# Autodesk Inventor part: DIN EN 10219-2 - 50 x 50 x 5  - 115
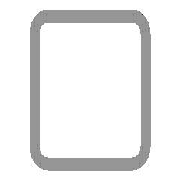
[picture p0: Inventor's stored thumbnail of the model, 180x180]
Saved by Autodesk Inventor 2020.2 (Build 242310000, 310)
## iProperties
IsCustomPart: 1
_CCFamilyMember: 16
_CCFamilyDisplayName: DIN EN 10219-2 (Quadratisches Hohlprofil - Kaltgeformt) - Kaltgeformte, geschweißte Baustahl-Hohlprofile aus unlegiertem Feinkorn-Baustahl
_FrameMemberDoc: Frame Member File
_Version: 15.0.0
_GetPNFromCC: 1
Created: 2019-01
Part Number: DIN EN 10219-2 - 50 x 50 x 5  - 115
Material: Generisch
Description: Kaltgeformte, geschweißte Baustahl-Hohlprofile aus unlegiertem Feinkorn-Baustahl
Document SubType Name: Modeling
Standard: DIN
Designer: lutzd
Standard Revision: 2006-07
Standards Organization: DIN
Language: de-DE
Size Designation: 50 x 50 x 5
Categories: <MemberInstance><Categories><Category DisplayName="Profile" InternalName="089c4875-fa83-4c05-b084-43b9cc11f5ed" Mnemonic="GRDR"><CategoryParameter DisplayName="
Stock Number: 50 x 50 x 5
Mass: 96.0962 g
Surface Area: 401.097 cm^2
Volume: 96.0962 cm^3
Density: 1 g/cm^3
Appearance: Vorgabe
G_L: 115,000 mm
G_W: 50,000 mm
G_H: 50,000 mm
Mass: 0,096 kg
VLT_Material: Generisch
+51C6CDD4-5B8E-40C9-8B9F-FFD168E0BA50+SCHNITTDETAIL1: Schnittwinkel 90,00 grd
DocNumber: ADSK-014429
Folder: .
Dimensions: 50x50x115 mm
Title: Profil-Bauteil
Author: lutzd
Revision Number: -
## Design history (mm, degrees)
node "Startebene"
node "Endebene"
sketch "Skizze"
  geometry: L1 (-25, -15)-(-25, 15); L2 (-15, 25)-(15, 25); L3 (25, 15)-(25, -15); L4 (15, -25)-(-15, -25); L5 (-15, 20)-(15, 20); L6 (20, 15)-(20, -15); L7 (15, -20)-(-15, -20); L8 (-20, -15)-(-20, 15); L9 (0, 37.899)-(0, -37.899) reference; L10 (-37.899, 0)-(37.899, 0) reference; A1 r 10 centre (-15, -15) between (-25, -15) and (-15, -25); A2 r 10 centre (-15, 15) between (-15, 25) and (-25, 15); A3 r 10 centre (15, 15) between (25, 15) and (15, 25); A4 r 10 centre (15, -15) between (15, -25) and (25, -15); A5 r 5 centre (-15, 15) between (-15, 20) and (-20, 15); A6 r 5 centre (15, 15) between (20, 15) and (15, 20); A7 r 5 centre (15, -15) between (15, -20) and (20, -15); A8 r 5 centre (-15, -15) between (-20, -15) and (-15, -20)
  constraints: 16 end point, 16 point on circle, 8 centre point, 8 tangent, 4 parallel, 3 equal radius, 2 perpendicular, 7 other
  dimensions: "d7" = 10 radius of A1 (= G_IR); "d10" = 50 distance between parallel lines of L2 L4 (= G_H); "d11" = 50 distance between parallel lines of L1 L3 (= G_W); "d12" = 5 distance between parallel lines of L3 L6 (= G_T); "d15" = 25 distance between parallel lines of L2 L10 (= 0.5 x d10); "d16" = 25 distance between parallel lines of L9 L3 (= 0.5 x d11)
extrude "Körper" new body sketch "Skizze" stored distance "d3" = 115 (= G_L); taper "d4" = 0 deg
node "Driven Length"
  sketch "Sketch3"
    geometry: L1 (0, 0)-(10, 0) reference
    constraints: 2 end point, 1 horizontal
  workplane "Work Plane3"
  sketch "Sketch4"
    geometry: L1 (-2, 0)-(12, 0) reference; L2 (-2, 115)-(12, 115) reference
    dimensions: "d18" = 115 distance between parallel lines of L1 L2 (derived)
workplane "Arbeitsebene4"
feature "Trennen1"
body "Solid1"
other parameters: "G_W" = 50 [user parameter; used in 1 equation term], "G_H" = 50 [user parameter; used in 1 equation term], "G_T" = 5 [user parameter; used in 1 equation term], "G_IR" = 10 [user parameter; used in 1 equation term], "G_L" = 115 (= d18) [user parameter; used in 1 equation term], "G_OFFSET_START" = 0 [user parameter; used in 1 equation term], "d13" = 0 (computed from G_OFFSET_START), "d14" = 115 (= G_OFFSET_END + B_L), "B_L" = 165 [user parameter; used in 1 equation term], "d17" = 90 deg
